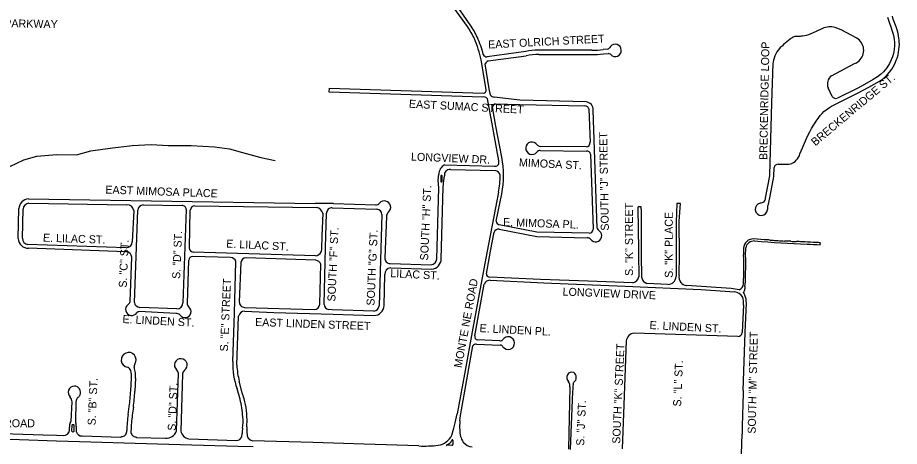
# Model space of a CAD drawing. Extents: x 0 to 712119, y 0 to 761125.
# Drawn here: x 689127 to 694633, y 726680 to 729358 of the extents above; entities that cross this region are included whole.
import ezdxf

# ---------------------------------------------------------------- set-up
doc = ezdxf.new("R2010")
doc.units = 0
for name, color, linetype in [('PAVED ROADS', 7, 'Continuous'), ('stream or creek', 7, 'Continuous'), ('street names', 7, 'Continuous')]:
    doc.layers.add(name, color=color, linetype=linetype)

msp = doc.modelspace()

# ---------------------------------------------------------------- linework, layer by layer
at = {"layer": 'PAVED ROADS'}
for points in [[(691953.5, 729313.1), (691809, 729522)], [(691936.5, 729302), (691804, 729488.5)], [(693875.8, 728442.9), (693932.4, 728442.6), (693943.4, 728443.1), (693953.8, 728444.4), (693961.1, 728446.6), (693964.6, 728448.6), (693973.1, 728453.6), (693982.3, 728459.7), (693989.9, 728466.5), (693997.4, 728475.1), (694003.6, 728485.1), (694009.1, 728495.3), (694012.6, 728506), (694027.8, 728544.8), (694059.6, 728617.6), (694074, 728644.2), (694083.8, 728664.3), (694098.7, 728688.2), (694114.4, 728711.2), (694129.5, 728733.4), (694138.8, 728745.7), (694150.8, 728758.8), (694161.9, 728770.3), (694176, 728781.7), (694191.1, 728793), (694209.5, 728803.8), (694250.5, 728824.9), (694372.3, 728884.8), (694443.1, 728923.4), (694510.4, 728960.1), (694526.5, 728971), (694540.4, 728983.7), (694556.3, 728999.6), (694572.5, 729017.6), (694585.7, 729036), (694595.2, 729051.1), (694602.8, 729065.6), (694609.7, 729079.9), (694614.4, 729090.9), (694619.5, 729105.2), (694625.2, 729125.5), (694628.8, 729141.9), (694631.1, 729157.6), (694632.6, 729174.7), (694633.5, 729190), (694633, 729204.6), (694632.1, 729216.9), (694630.8, 729230.2), (694628.7, 729244.6), (694625.1, 729259.5), (694619, 729281.1), (694612.5, 729300.5), (694595.5, 729348.2), (694590, 729366.7)], [(694560.1, 729360.1), (694565.4, 729341.3), (694571.9, 729324), (694580.7, 729299.4), (694589.2, 729273.4), (694595.2, 729254.1), (694599, 729236.6), (694601.3, 729221.9), (694603.2, 729203.8), (694603.2, 729183.8), (694601.1, 729158.1), (694596.5, 729134.4), (694590.1, 729112.7), (694582.4, 729093.8), (694571.7, 729070.7), (694554.4, 729044.2), (694533.5, 729019.8), (694515.5, 729002.1), (694496.7, 728988.1), (694470.1, 728971.8), (694416.6, 728939.5), (694374.6, 728917.3), (694246.1, 728853.9)], [(694113.8, 729271.8), (694080.6, 729255.6), (694066.8, 729251), (694052.2, 729246.9), (694040.1, 729244), (694029.3, 729241.8), (694020.8, 729241.2), (694013.1, 729240.5), (694004.7, 729240.3), (693995.3, 729240), (693987, 729239.9), (693980.1, 729239.2), (693974.5, 729237.8), (693969.9, 729235.8), (693963.7, 729232.2), (693956.5, 729227.9), (693951.1, 729223.9), (693910.6, 729189.2), (693900.5, 729180.2), (693889.8, 729170.7), (693884, 729164.5), (693875.9, 729154.6), (693868.3, 729143.2), (693861.2, 729131.2), (693855.4, 729119.8), (693850.9, 729104.4), (693847.4, 729090.9), (693844.7, 729078.5), (693843.8, 729070.4), (693835.9, 728824.8), (693822.2, 728373.3), (693821.6, 728369.1), (693795.6, 728229.7), (693794.4, 728222), (693792.7, 728216.9), (693789.2, 728211.5), (693784.4, 728206), (693780.1, 728202.4), (693775.3, 728200.6), (693767.7, 728199.4), (693763.6, 728198.7)], [(694152.9, 729290.5), (694113.8, 729271.8)], [(694368.4, 729229.4), (694270.2, 729280.7), (694232.3, 729295.7)], [(692810, 729161), (692784, 729158.5)], [(692300, 729146.5), (692059, 729113.5)], [(692065.5, 729087.1), (692302, 729120)], [(692713, 729155), (692375, 729154)], [(692382.5, 729127), (692712.5, 729127)], [(692785.5, 729131.5), (692815, 729134)], [(692053, 728908.5), (692021, 729094)], [(692079.5, 728873.5), (692072, 728912.5), (692047.5, 729069)], [(694209.6, 728994.1), (694209.6, 728994.1), (694354.2, 729070.5), (694365, 729076.3), (694382, 729088)], [(692029.5, 728861), (691072.5, 728892), (691074, 728917.5), (692035, 728886)], [(694214.1, 728865.8), (694188.3, 728918.9)], [(692128.5, 728486), (692095.3, 728672.1), (692061, 728850.5)], [(692676.5, 728831), (692263.5, 728843), (692102.5, 728861)], [(692150.1, 728486.1), (692114.2, 728679), (692091.6, 728800.6)], [(692110, 728819.3), (692263.6, 728815.6)], [(692263.6, 728815.6), (692670.1, 728806.2)], [(692694.2, 728788.5), (692701.4, 728578.5)], [(692747.1, 728043.2), (692721.9, 728780.3)], [(692679.2, 728550), (692390, 728553.5)], [(692390.9, 728527), (692679.9, 728524.4)], [(692705, 728504.8), (692721.1, 728036.6)], [(691792, 728437.3), (692104.8, 728429.1)], [(691829.2, 728409.6), (692108.4, 728402.9)], [(693810.3, 728158.1), (693811, 728163.8), (693811.7, 728171.8), (693812.3, 728179.5), (693812.7, 728181.9), (693814.5, 728187.1), (693816.7, 728193.2), (693818.2, 728202.1), (693826.1, 728241.7), (693849, 728365.3), (693851.6, 728421.4)], [(691744.5, 727851.1), (691758.2, 728293.8), (691753.8, 728342.6), (691756.8, 728379.9)], [(691769.4, 728366.8), (691769.1, 728337.9), (691769.1, 728337.9)], [(691772.5, 727850.9), (691785.1, 728298.3), (691789.1, 728339.7), (691791.8, 728370)], [(691777.2, 728337.8), (691777.7, 728367.1)], [(689193.7, 728225.4), (690984.6, 728197.4)], [(692129.9, 728266.9), (692058.5, 727899.9), (692026.6, 727722.5), (691969, 727417.4), (691917.3, 727130), (691870.8, 726883.3)], [(692115.8, 728085.9), (692150.1, 728257.2)], [(689197.1, 728197.9), (689809.1, 728188.6)], [(689910.3, 728188), (690153.9, 728183.8)], [(690233.2, 728183.1), (690994.5, 728171.1)], [(690233.2, 728183.1), (690233.2, 728183.1)], [(691091.8, 728169.9), (691370.4, 728162.3)], [(691099.9, 728195.8), (691360.7, 728187.6)], [(693257.6, 727746.8), (693261.1, 727876.1), (693259.2, 728086.3), (693266, 728197.1), (693244.4, 728197.1), (693238.5, 728080.6), (693240.4, 727886.7), (693239, 727739.8)], [(689130.8, 727977.6), (689135, 728164.7)], [(689156.7, 727980), (689160.4, 728162.3)], [(689851.4, 728153.1), (689842.3, 727956.7)], [(689855.5, 727579.1), (689877, 728156)], [(690178.8, 728160.2), (690159.1, 727577.1)], [(690199, 727919.6), (690205.2, 728156.7)], [(691032.5, 728135.6), (691025.8, 727991.7), (691024.1, 727913.6), (691022, 727894.9)], [(691041.3, 727565.5), (691050.1, 727921), (691052, 727992.7), (691055.8, 728135.9)], [(691402, 728127.5), (691384.7, 727557.6)], [(691430, 728116.5), (691420.9, 727858.2)], [(693022.1, 728133.3), (693022.3, 728150.5)], [(692695.7, 728010.5), (692368.4, 728017.9), (692134.7, 728063.9)], [(693003.2, 728065.4), (693003.7, 727880), (693006, 727739.7)], [(693024.5, 727732), (693023.3, 727880.1), (693022.3, 728105.1)], [(692054, 727758.4), (692079.3, 727899), (692102.8, 728017.4)], [(692133.4, 728036.3), (692369.8, 727990.3), (692684.5, 727982.8)], [(693789.1, 727970.6), (693724.6, 727975.1)], [(693955.1, 727960.9), (693942.8, 727961.6)], [(689805.5, 727920.6), (689190.7, 727941.3)], [(689800.2, 727895.8), (689195.2, 727916.8)], [(690987.1, 727870.1), (690222.1, 727893.2)], [(693659.7, 727917.1), (693661, 727876)], [(693673.4, 727869.5), (693674.5, 727920.1)], [(689829.8, 727585.3), (689839.8, 727860.8)], [(690194.8, 727842.8), (690186, 727573)], [(690456.7, 727858.8), (690219.4, 727865.2)], [(690989.4, 727842.3), (690552.9, 727857.3)], [(690470.1, 727210.8), (690480.6, 727510.8), (690489.7, 727834.3)], [(690520.7, 727828.4), (690511.1, 727582.3)], [(691014.3, 727568.5), (691021.1, 727817.4)], [(691452.6, 727821.7), (691708.5, 727813.8)], [(691456.7, 727794.9), (691712.8, 727787.2)], [(691415.1, 727558.8), (691419.3, 727752.5)], [(692969.2, 727701.8), (692689.2, 727710.7), (692392.4, 727723), (692075.2, 727737.3)], [(691982.2, 727370.1), (692041.4, 727692.8)], [(692078.6, 727717.1), (692413.7, 727702.1), (692921.8, 727681), (693393.9, 727659.6), (693605.6, 727644.4)], [(693187.8, 727691.8), (693057, 727698.1)], [(693582.7, 727665.5), (693303.4, 727684.4)], [(693659.1, 727564.8), (693652, 727390.3)], [(693658.8, 727028.7), (693670, 727391.8), (693677.9, 727575.1)], [(690115.1, 727510.4), (689886.5, 727521.7)], [(690121.6, 727538.5), (689889.6, 727547.8)], [(690542.9, 727523.5), (690725.9, 727516.7), (691098.3, 727506.2), (691351.8, 727497.9)], [(690543.3, 727548), (690979.5, 727534.1), (690979.5, 727534.1)], [(691351.5, 727523.9), (691090.6, 727531.6), (691067.8, 727533.7)], [(690496, 727186.4), (690506.9, 727494)], [(692138.5, 727339.8), (691997.1, 727345.1)], [(693624.8, 727366.4), (692976.2, 727387)], [(691888.7, 726839.1), (691893.6, 726873), (691926.4, 727060), (691970, 727307.3)], [(691992.7, 727318.9), (692140.3, 727312.6)], [(692157.6, 727301.5), (692157.6, 727301.5)], [(692927.6, 727338.6), (692913.2, 726938.5), (692903.1, 726664.1)], [(690118.6, 726776.6), (690131, 727134.6)], [(690157, 727133.8), (690146.4, 726774.8)], [(689832.8, 727026.8), (689837.1, 727106.2)], [(689863.1, 727104.8), (689858.8, 727025.4)], [(690529.1, 727013.5), (690510.9, 727086.5)], [(692596.4, 727067.7), (692600.9, 727080.2)], [(690515.6, 726974.7), (690497.3, 727038.8)], [(692575.2, 727052.5), (692566.7, 726662.4)], [(692579.3, 726659.5), (692593.1, 727022.8)], [(689460.2, 726838.2), (689467.1, 726958.8)], [(689490.5, 726956.9), (689487.4, 726837.9)], [(689816.9, 726878.8), (689823.5, 726928.3)], [(689849.3, 726924.9), (689842.7, 726875.3)], [(689449.8, 726779.4), (689450.5, 726799.5)], [(689492, 726804), (689492.7, 726772.4)], [(691855, 726809.4), (691855, 726809.4)], [(688966.8, 726762.5), (689285.7, 726752.5), (689368.4, 726748.9), (689412.4, 726747.9)], [(689529.5, 726744.9), (689771.4, 726737.4), (689775.2, 726741.4)], [(689808.1, 726772.6), (689808.3, 726778)], [(689834.3, 726777), (689834.1, 726772.3)], [(689865, 726739.1), (689869.1, 726734.7), (690050, 726730.3)], [(690526.8, 726740), (690528.7, 726759.8)], [(690561.6, 726741.4), (690559.7, 726777.7)], [(693647.3, 726633.3), (693650.8, 726756.8)], [(688856.3, 726729.9), (689139.1, 726722.6), (689369.4, 726714.8), (689584.6, 726707.6), (690001, 726696), (690502.1, 726682.1), (690597.8, 726679.9)], [(690195.6, 726726.4), (690493.5, 726717.4)], [(691633.1, 726682.3), (691289.9, 726693.6), (690970.7, 726703.5), (690593.2, 726714.2)], [(691837.5, 726686.5), (691807.1, 726686.3)], [(691844.8, 726719.3), (691844.3, 726692.3)]]:
    msp.add_lwpolyline(points, dxfattribs=at)
msp.add_lwpolyline([(689472.2, 726817.4), (689474.6, 726816.9), (689476.3, 726815.8), (689477.2, 726813.8), (689476.8, 726773.7), (689475.3, 726770.9), (689471.9, 726769.1), (689468.6, 726769.9), (689466.3, 726772), (689465.8, 726774.2), (689468, 726814.4), (689469.4, 726816.4)], close=True, dxfattribs=at)
for centre, radius, start, end in [((691343.4, 728916.2), 707.5, 25.8804, 33.0469), ((691462.3, 728986.6), 589.9, 24.7491, 33.6148), ((694200.8, 729169.8), 129.9, 75.9445, 111.6622), ((691357.7, 728958.3), 677, 11.5605, 23.1974), ((691511.4, 729006.7), 536.9, 13.0075, 24.9937), ((694321.9, 729153.6), 88.9, 312.4464, 58.5097), ((692803.2, 729187.8), 27.7, 284.2637, 314.234), ((692858.2, 729153.3), 38.6, 240.9931, 157.6396), ((692055.9, 729136.5), 23.2, 202.7772, 277.733), ((692378.5, 728739.8), 414.2, 90.4902, 100.931), ((692370.3, 728801.1), 326.1, 87.8534, 102.0861), ((692725.5, 729511), 384.2, 268.0652, 278.9897), ((692724.7, 729639.3), 484.5, 268.615, 277.0293), ((692809.6, 729097), 37.4, 37.0305, 81.7323), ((692077.3, 729057.3), 32.1, 111.6553, 158.5104), ((694247.6, 728942.8), 63.9, 126.5259, 201.9635), ((692035.8, 728903.8), 17.8, 267.4877, 15.1927), ((692038.7, 728836), 26.7, 33.059, 110.0711), ((692105.2, 728893.3), 32.4, 217.6622, 265.2915), ((692674, 728783.1), 48, 356.7106, 87.0306), ((694237, 728878.4), 26.1, 208.7081, 290.242), ((692115.8, 728795.2), 24.8, 103.4868, 167.623), ((692669.8, 728780.6), 25.6, 17.9769, 89.483), ((692339.1, 728542), 38.9, 32.1008, 322.2425), ((692391.8, 728579.2), 25.8, 219.7959, 265.9259), ((692674.5, 728576.5), 26.9, 280.023, 4.1674), ((692387.8, 728504.8), 22.4, 82.0404, 143.2907), ((692679.6, 728498.1), 26.2, 14.675, 89.3513), ((692107.6, 728454.3), 25.3, 263.669, 7.2312), ((651905.8, 722515), 40663.5, 8.40324, 8.44383), ((691578.1, 728371.6), 583.4, 348.6957, 11.3242), ((691823.3, 728378.6), 66.5, 118.0988, 178.881), ((691827.1, 728374.1), 35.5, 86.5551, 186.6757), ((692103.5, 728365.5), 37.7, 11.181, 82.5128), ((693877.2, 728417), 26, 93.1047, 170.2108), ((691773.1, 728336.1), 4.45, 154.8951, 22.5911), ((691773.6, 728367.9), 4.26, 349.9518, 193.7376), ((691646.9, 728368.7), 493.6, 348.1011, 0.4814), ((689197.9, 728162.7), 62.9, 93.7832, 178.2352), ((689199, 728159.2), 38.7, 92.8241, 175.4053), ((689812.3, 728149.4), 39.3, 5.3439, 94.6991), ((689911.8, 728153.1), 34.9, 92.4341, 175.1641), ((689910.3, 728188), 0.000000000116, 270, 0.8856), ((690155.8, 728160.9), 23.1, 358.3375, 94.6663), ((690233.2, 728155.1), 28, 89.9516, 176.685), ((690995.5, 728023.5), 174.2, 85.159, 93.5859), ((690986.8, 728124.9), 46.9, 13.2726, 80.6079), ((691027.8, 727202.3), 994.9, 87.3595, 91.0112), ((691090.8, 728134.9), 35, 88.4413, 178.4636), ((691084.9, 728079.7), 117, 82.6482, 95.5457), ((691362.9, 728217.5), 30, 265.8381, 322.8727), ((691417.1, 728173.3), 40, 309.6511, 139.3863), ((693006.1, 727964.4), 211.7, 86.064, 91.2864), ((692274.9, 728164), 726.6, 359.8057, 0.9527), ((692526.3, 728130.7), 496.4, 2.2909, 5.1926), ((693771.9, 728161), 38.6, 102.3617, 355.5451), ((691363.3, 728124.1), 38.9, 4.9426, 79.4339), ((691465, 728115.6), 35, 129.665, 178.5089), ((692422.9, 728130.1), 579.4, 359.6983, 3.105), ((692021.2, 728082.3), 982.2, 359.0105, 2.609), ((691848.9, 728112.4), 1173.4, 359.6438, 1.0207), ((692139.5, 728087.2), 23.8, 183.2183, 258.4359), ((692129.3, 728008.6), 28, 81.6138, 161.7254), ((692695.1, 728036.5), 26.1, 271.3449, 0.0702), ((692736.5, 727995.2), 38.4, 216.5271, 49.901), ((692774.2, 728049.1), 27.7, 192.1671, 242.1692), ((689193.9, 727979.9), 63.1, 182.0532, 271.2449), ((689194.8, 727979.1), 38.1, 178.6458, 263.8693), ((689805.3, 727957.6), 37.1, 270.3451, 358.5301), ((692684, 727955), 27.8, 38.7057, 89.0347), ((693720.9, 727913.9), 61.3, 86.5654, 176.9994), ((693726.4, 727909.8), 52.9, 87.0001, 168.7885), ((694433.7, 736990.1), 9054.9, 265.53783, 267.61514), ((693781.9, 727612), 358.6, 83.2111, 88.8602), ((693884.3, 729026.6), 1060.1, 266.7574, 267.8887), ((693894.7, 728479.4), 514.6, 264.4836, 267.8874), ((695859, 755849.8), 27955.1, 265.93181, 266.01553), ((688543.9, 518294.5), 209736.6, 88.528719, 88.532157), ((649877.4, -986453.3), 1714981.1, 88.5276584, 88.5281167), ((694033.7, 729077.1), 1119, 265.9747, 267.7655), ((693978.5, 727128.7), 830.4, 86.7516, 89.2025), ((693947.8, 726107.9), 1851.5, 85.445, 87.5918), ((694092.5, 727388.7), 564.8, 85.1376, 89.7661), ((693025.6, 728107.9), 1125.6, 351.367, 352.0156), ((689803.4, 727859.5), 36.4, 2.044, 94.99), ((690224.9, 727919), 26, 178.8429, 263.8477), ((690985, 727909.9), 39.9, 273.0916, 337.9061), ((694473.1, 735407.9), 7476.5, 266.80872, 267.43528), ((690219.8, 727840.1), 25.1, 90.9823, 173.8391), ((690456.7, 727824.3), 34.5, 16.8792, 90.0954), ((690554.3, 727823.3), 34, 92.5093, 171.2912), ((690980.7, 727798.7), 44.5, 24.9373, 78.6444), ((691452.7, 727853.8), 32, 172.1191, 269.8585), ((691706.1, 727852.1), 38.4, 273.5403, 358.4604), ((691706.9, 727852.6), 65.6, 275.1347, 358.5266), ((690536.3, 727806.1), 3125.5, 357.9623, 1.2815), ((689715.3, 727815.2), 3958.5, 358.8769, 0.7863), ((691459.3, 727754.9), 40, 93.7343, 183.5488), ((692073.8, 727757.1), 19.9, 176.2007, 273.8224), ((692960.7, 727746.9), 45.8, 280.7432, 351.043), ((693065.5, 727738.8), 41.6, 189.4262, 258.1086), ((693188.8, 727742), 50.2, 268.836, 357.4702), ((693313.1, 727738.9), 56.1, 171.8737, 218.2138), ((693016.5, 727755.3), 656.8, 353.2662, 358.4557), ((692074.8, 727682.5), 34.9, 83.6456, 162.7432), ((693306.9, 727730.3), 46, 214.6222, 265.6811), ((693619.4, 727695.8), 40.5, 289.3193, 358.7995), ((694119.4, 727629.3), 453.3, 173.7958, 177.0407), ((693491.3, 726918.6), 752.5, 79.1643, 83.0263), ((693598.2, 727578.9), 66, 30.9647, 83.5039), ((693620.1, 727664.5), 48, 327.275, 345.7699), ((693598.2, 727592.4), 77.6, 23.9159, 36.5232), ((693559.5, 727578.9), 118.4, 358.1619, 22.2737), ((689839.1, 727535.6), 38.5, 126.8298, 327.2798), ((689805.1, 727588.8), 25, 296.0808, 351.8409), ((689891.1, 727583.6), 35.9, 187.3517, 267.7485), ((690120.4, 727577.2), 38.7, 271.7269, 359.8999), ((690211, 727570.5), 25.1, 174.3998, 231.5098), ((690543.9, 727580.9), 32.9, 177.4743, 268.9062), ((690976, 727572.4), 38.5, 275.1982, 354.1632), ((691077.3, 727568.6), 36.1, 184.8944, 254.752), ((693537.7, 727578.2), 122.1, 353.708, 16.4721), ((689889.2, 727495.8), 26, 96.0018, 133.11), ((690116.5, 727477.6), 32.9, 44.6925, 92.4982), ((690171.7, 727521.3), 37.9, 212.9542, 51.2512), ((690542.8, 727486.7), 36.7, 89.8249, 168.5998), ((691347.7, 727560.9), 37.2, 275.9222, 354.929), ((691352.9, 727560), 62.2, 268.9347, 358.893), ((692000.7, 727364.2), 19.4, 162.297, 259.3291), ((692142.1, 727361.9), 22.4, 260.9002, 308.0421), ((692190.4, 727324.3), 39.9, 214.866, 149.8413), ((692981.3, 727333.3), 54, 95.4681, 174.3796), ((693624, 727394.7), 28.4, 271.7494, 350.9225), ((691990.3, 727295.6), 23.4, 84.0324, 150.1403), ((692142.3, 727296.6), 16.1, 17.4961, 97.014), ((689819.9, 727220), 46.5, 326.4726, 259.7329), ((689881.2, 727179.4), 27, 146.4726, 196.4104), ((690146.2, 727187.7), 39.9, 304.7018, 228.3391), ((690931.1, 727195.6), 461.2, 178.1172, 199.8733), ((690930.2, 727200.3), 434.4, 181.8348, 195.1948), ((689806.8, 727147.6), 27, 12.7006, 79.7329), ((689664.8, 727115.6), 172.6, 356.8646, 12.7006), ((689664.8, 727115.6), 198.6, 356.8647, 16.4104), ((690085.2, 727127), 46.4, 9.43, 41.8738), ((690191.3, 727128.3), 34.8, 130.0374, 170.8913), ((692594.9, 727109.8), 38.6, 153.8002, 222.0757), ((692588, 727112.9), 31, 67.2773, 153.4005), ((692577.1, 727110.5), 38.5, 308.1438, 53.5627), ((692543.3, 727060.4), 32.9, 345.9772, 45.5975), ((692967, 727017.2), 374, 172.2475, 179.148), ((689482.2, 727016.8), 39.4, 91.5958, 227.0665), ((689480.8, 727016.5), 39.7, 337.7747, 89.4544), ((688570.3, 727096), 1264.4, 352.38, 356.8631), ((688570.3, 727096), 1290.4, 352.38, 356.8632), ((690136.3, 726857.4), 422.7, 0.9611, 21.6801), ((712159.5, 726347.9), 18513.2, 177.89261, 178.73449), ((689358, 726932.1), 112.3, 13.7734, 29.86), ((689528.7, 726956.6), 38.2, 128.1956, 179.543), ((689459.7, 727037), 67.8, 311.9694, 328.4685), ((690036.7, 726843), 496.6, 2.4448, 15.3763), ((690869.9, 726737.9), 1062.4, 172.3795, 177.8353), ((690869.9, 726737.9), 1036.4, 172.3795, 177.8353), ((690258.4, 726832.6), 276.3, 351.7286, 6.5665), ((690002.6, 726842.5), 556.8, 355.7482, 2.2621), ((691379.9, 726949.9), 495.5, 343.5277, 352.2804), ((689510, 726804.2), 59.7, 156.6983, 184.4586), ((689437.3, 726842.7), 23.3, 320.1306, 348.6842), ((689504, 726836.8), 16.7, 175.9804, 217.2199), ((689435.7, 726812.3), 57, 351.6643, 14.6401), ((690672.9, 726762.9), 144.2, 168.0028, 181.2281), ((690626.1, 726797.8), 68.3, 177.0836, 188.5319), ((690267.2, 727222.8), 1640.7, 343.2475, 345.4043), ((692315.7, 726802.3), 428.7, 175.0689, 182.7822), ((689415.2, 726782.5), 34.8, 265.3591, 354.8341), ((689526.9, 726779.8), 35, 192.3066, 274.2196), ((689776.1, 726773.4), 32, 268.4906, 358.5761), ((689866.1, 726771), 32, 177.8323, 268.1784), ((690053.9, 726798.5), 68.3, 266.7488, 341.2926), ((690205.6, 726785.7), 60.2, 190.4873, 260.4646), ((690493.5, 726753.3), 35.9, 270.0166, 338.1989), ((690473.3, 726772.4), 86.6, 3.4783, 10.1044), ((690604.1, 726758.8), 45.9, 202.2892, 256.2288), ((691734.9, 726800.3), 115, 279.3326, 334.0118), ((692018.3, 726778.9), 130.8, 178.8638, 213.5482), ((691661.5, 727527), 845.2, 268.073, 276.2556), ((691806.5, 726687.4), 1.3, 129.6731, 295.6706), ((691785.5, 726744.6), 59.7, 289.8108, 334.259), ((691838.3, 726692.5), 6.04, 262.3822, 358.2213), ((691842.1, 726718.7), 2.79, 13.9939, 179.4164), ((691971.7, 726756.4), 79.8, 218.5798, 266.167)]:
    msp.add_arc(centre, radius, start, end, dxfattribs=at)
at = {"layer": 'stream or creek'}
msp.add_lwpolyline([(689077, 728428.3), (689166, 728468.9), (689247.3, 728492.4), (689372.3, 728503.3), (689494.1, 728501.7), (689584.7, 728525.2), (689719.1, 728544), (689773.9, 728550.9), (689842.6, 728559.6), (689959.8, 728564.3), (690065.9, 728558.9), (690084.8, 728558), (690209.7, 728558), (690356.7, 728550.2), (690450.4, 728537.7), (690531.7, 728514.3), (690645.7, 728483), (690734.8, 728464.3)], dxfattribs=at)

# ---------------------------------------------------------------- texts
at = {"layer": 'street names'}
for s, rotation, p in [('VETERANS PARKWAY', 358.9838, (688663.8, 729304.5)), ('EAST OLRICH STREET', 2.9838, (692066.5, 729164.3)), ('BRECKENRIDGE LOOP', 88.9227, (693808.2, 728468.1)), ('BRECKENRIDGE ST.', 40, (694108.4, 728553.3)), ('EAST SUMAC STREET', 356.9997, (691569.4, 728795.4)), ('SOUTH "J" STREET', 90.9838, (692819.1, 728027.3)), ('LONGVIEW DR.', 357.6694, (691582.5, 728465.1)), ('MIMOSA ST.', 357.2196, (692256.6, 728428.8)), ('EAST MIMOSA PLACE', 357.9838, (689673.8, 728259.1)), ('SOUTH "H" ST.', 87.4864, (691689.8, 727839.9)), ('S. "K" STREET', 90, (692969.6, 727744.3)), ('S. "K" PLACE', 90, (693218.3, 727732.6)), ('E. MIMOSA PL.', 357.9838, (692158, 728056.2)), ('E. LILAC ST.', 358.0711, (689284, 727958.7)), ('S. "D" ST.', 87.4864, (690141.3, 727724.9)), ('SOUTH "F" ST.', 87.4864, (691110.7, 727583.6)), ('SOUTH "G" ST.', 87.4864, (691355.1, 727558)), ('S. "C" ST.', 87.4864, (689807.8, 727670.1)), ('E. LILAC ST.', 357.0768, (690428.6, 727922.1)), ('LILAC ST.', 357.0768, (691453.3, 727737)), ('S. "E" STREET', 87.4864, (690439.7, 727271.6)), ('MONTE NE ROAD', 79.5673, (691900, 727167.2)), ('LONGVIEW DRIVE', 357.6694, (692529.5, 727622.1)), ('E. LINDEN ST.', 357.0768, (689780.5, 727450.3)), ('EAST LINDEN STREET', 357.9838, (690608.8, 727432)), ('E. LINDEN ST.', 357.0768, (693072, 727412.9)), ('E. LINDEN PL.', 357.0768, (692010.5, 727393.7)), ('SOUTH "M" STREET', 88.7634, (693735.9, 726758.2)), ('SOUTH "K" STREET', 87.4864, (692889.5, 726695.3)), ('S. "L" ST.', 87.4864, (693269.8, 726928.1)), ('S. "B" ST.', 87.4864, (689613.2, 726809.9)), ('S. "D" ST.', 87.4864, (690113.5, 726776.5)), ('S. "J" ST.', 87.4864, (692664.5, 726682.7)), ('E. NEW HOPE ROAD', 359.9838, (688577.3, 726799.4))]:
    msp.add_text(s, height=50, rotation=rotation, dxfattribs=at).set_placement(p)

doc.saveas('drawing.dxf')
